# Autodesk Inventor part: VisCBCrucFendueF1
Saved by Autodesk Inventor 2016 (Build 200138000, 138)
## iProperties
Created: 2013-08
Part Number: VisCBCrucFendueF1
Material: Générique
Document SubType Name: Modeling
Designer: hilarion
Density: 1 g/cm^3
Appearance: Par défaut
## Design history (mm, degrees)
node "VisCBCrucFendueF11"
node "VisCBCrucFendueF1"
node "Base1"
